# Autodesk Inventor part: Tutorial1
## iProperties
Shininess: 64.0
Length Units: 11269
Angle Units: 11279
Time Units: 11290
Mass Units: 11283
Length Display Precision: 3
Angle Display Precision: 2
Compacted: True
Part Number: Tutorial1
Document SubType Name: Modeling
Created: 2002-12
Designer: deepak
Density: 0.0
Volumn: 0.0
Area: 0.0
PropertySet Name: Model Information
Control State: 0
Master: False
Checked Out: False
Author: deepak
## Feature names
1. Extrusion1
